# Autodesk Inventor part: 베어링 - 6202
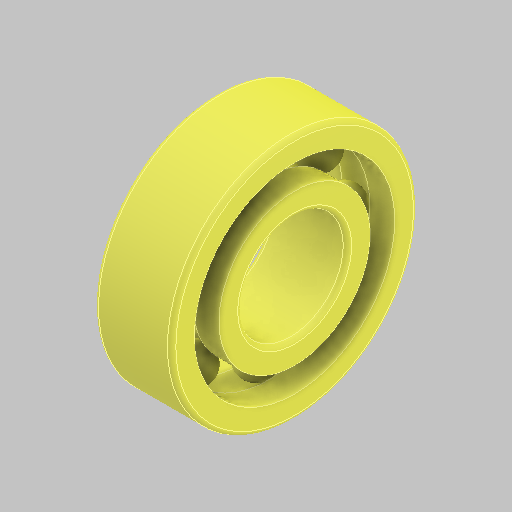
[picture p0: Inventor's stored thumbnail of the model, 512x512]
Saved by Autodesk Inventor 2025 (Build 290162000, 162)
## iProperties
Created: 2024-07
Part Number: 베어링 - 6202
Material: 강, 연강
Description: 깊은 그루브 볼 베어링
Document SubType Name: Modeling
Designer: 현기
Density: 7.86 g/cm^3
Appearance: 기본값
Author: jhkim
Sending System: Autodesk Inventor 2025
Preprocessor: ST-DEVELOPER v20
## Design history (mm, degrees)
feature "Solid1"
feature "Solid1:1"
feature "Solid1:2"
feature "Solid1:3"
feature "Solid1:4"
feature "Solid1:5"
feature "Solid1:6"
feature "Solid1:7"
feature "Solid1:8"
feature "Solid1:9"
node "솔리드1"
node "솔리드2"
node "솔리드3"
node "솔리드4"
node "솔리드5"
node "솔리드6"
node "솔리드7"
node "솔리드8"
node "솔리드9"
node "솔리드10"
